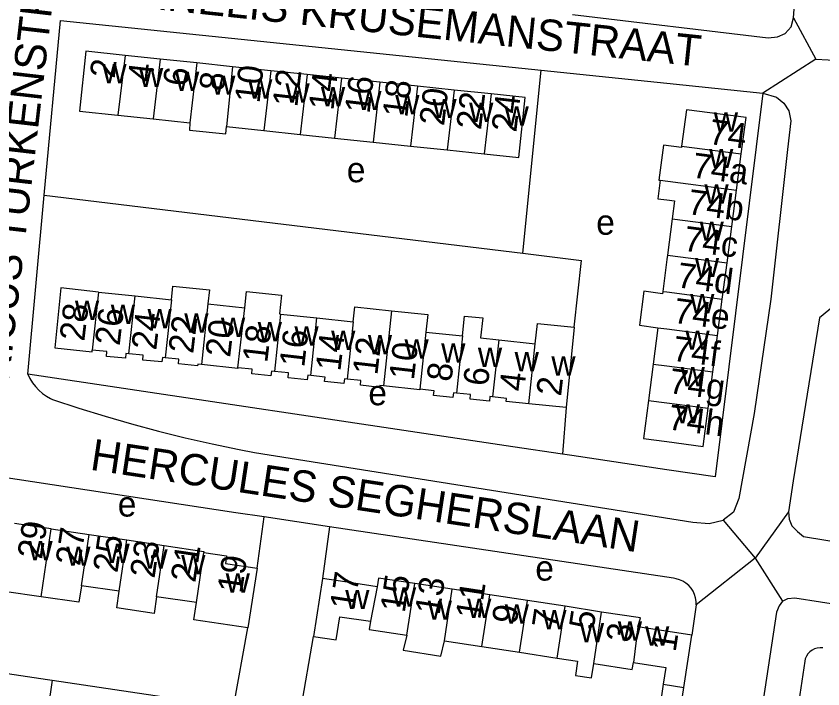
# Model space of a CAD drawing. Extents: x 163012 to 165277, y 382513 to 383987.
# Drawn here: x 163246.1 to 163374.9, y 383224 to 383331.4 of the extents above; entities that cross this region are included whole.
import ezdxf

# ---------------------------------------------------------------- set-up
doc = ezdxf.new("R2010")
doc.units = 0
for name, color, linetype in [('BLT_Basislijn', 7, 'Continuous'), ('BLT_Bebouwing', 7, 'Continuous'), ('BLT_Centroide', 7, 'Continuous'), ('BLT_Huisnummer', 7, 'Continuous'), ('BLT_Huisnummer_ tussenligend', 7, 'Continuous'), ('BLT_Onderverdeling_panden', 7, 'Continuous'), ('BLT_Straatnaam', 7, 'Continuous'), ('BLT_Vlakafsluiter', 7, 'Continuous')]:
    doc.layers.add(name, color=color, linetype=linetype)

msp = doc.modelspace()

# ---------------------------------------------------------------- linework, layer by layer
at = {"layer": 'BLT_Basislijn'}
for p, q in [((163250.62, 383302.77), (163253.2, 383330.67)), ((163253.2, 383330.67), (163329.96, 383322.72)), ((163327.02, 383293.5), (163329.96, 383322.72)), ((163329.96, 383322.72), (163350, 383320.64)), ((163247.99, 383274.21), (163250.62, 383302.77)), ((163250.62, 383302.77), (163327.02, 383293.5)), ((163327.02, 383293.5), (163336.38, 383292.33)), ((163335.19, 383281.7), (163336.38, 383292.33)), ((163379.1, 383287.13), (163374.38, 383283.18)), ((163325.42, 383262.62), (163247.99, 383274.21)), ((163333.94, 383268.86), (163333.34, 383261.44)), ((163333.34, 383261.44), (163325.42, 383262.62)), ((163334.85, 383261.21), (163333.34, 383261.44)), ((163350, 383258.95), (163334.85, 383261.21)), ((163357.71, 383257.79), (163350, 383258.95)), ((163281.2, 383252.08), (163240.34, 383258.32)), ((163285.7, 383251.41), (163281.2, 383252.08)), ((163284.58, 383243.24), (163285.7, 383251.41)), ((163296.15, 383249.84), (163285.7, 383251.41)), ((163296.15, 383249.84), (163295.02, 383241.61)), ((163350, 383241.78), (163296.15, 383249.84)), ((163351.05, 383241.63), (163350, 383241.78)), ((163354.7, 383237.36), (163353.96, 383232.55)), ((163280.84, 383221.02), (163283.14, 383233.7)), ((163291.43, 383219.86), (163293.58, 383232.33)), ((163372.01, 383228.39), (163368.01, 383201.4)), ((163251.88, 383225.34), (163249.99, 383212.44)), ((163251.88, 383225.34), (163280.84, 383221.02))]:
    msp.add_line(p, q, dxfattribs=at)
for points in [[(163370.2, 383331.1), (163375.21, 383397.63), (163379.98, 383443.37), (163379.47, 383447.48), (163378.38, 383448.91), (163376.87, 383450.09), (163374.9, 383450.62)], [(163334.93, 383331.61), (163366.16, 383327.92), (163367.65, 383328.08), (163368.88, 383328.58), (163369.86, 383329.67), (163370.2, 383331.1)], [(163350, 383320.64), (163365.31, 383319.06)], [(163365.31, 383319.06), (163357.71, 383257.79)], [(163365.31, 383319.06), (163367.49, 383318.41), (163368.65, 383317.47), (163369.45, 383316.22), (163369.78, 383314.65), (163369.27, 383310.06), (163366.6, 383286.2), (163363.93, 383267.93), (163361.51, 383254.36), (163360.61, 383252.18), (163358.98, 383250.87)], [(163374.38, 383283.18), (163370.14, 383257.16), (163369.43, 383252.25)], [(163247.99, 383274.21), (163248.33, 383273.51), (163248.73, 383272.84), (163249.2, 383272.22), (163249.74, 383271.65), (163250.33, 383271.14), (163250.96, 383270.69), (163251.64, 383270.3), (163251.93, 383270.17)], [(163251.93, 383270.17), (163256.12, 383268.79), (163260.34, 383267.49), (163264.57, 383266.27), (163268.83, 383265.13), (163273.11, 383264.06), (163277.41, 383263.07), (163281.72, 383262.16), (163284.16, 383261.68)], [(163284.16, 383261.68), (163354.12, 383250.58), (163356.74, 383250.36), (163358.98, 383250.87)], [(163369.43, 383252.25), (163369.53, 383251.03), (163369.96, 383249.99), (163370.84, 383249.08), (163371.8, 383248.31)], [(163371.8, 383248.31), (163405.82, 383242.7), (163463.3, 383234.3)], [(163354.7, 383237.36), (163354.69, 383237.93), (163354.59, 383238.5), (163354.42, 383239.04), (163354.17, 383239.56), (163353.86, 383240.04), (163353.48, 383240.47), (163353.04, 383240.84), (163352.56, 383241.15), (163352.04, 383241.39), (163351.49, 383241.55), (163351.05, 383241.63)], [(163368.47, 383237.95), (163369.3, 383238.38), (163370.44, 383238.51), (163378.6, 383237.22)], [(163368.47, 383237.95), (163367.9, 383237.24), (163367.52, 383236.23), (163353.87, 383146.27)], [(163374.9, 383230.51), (163374.45, 383230.54), (163374, 383230.48), (163373.57, 383230.35), (163373.17, 383230.15), (163372.81, 383229.88), (163372.5, 383229.54), (163372.26, 383229.16), (163372.09, 383228.75), (163372.01, 383228.39)], [(163225.21, 383229.34), (163251.12, 383225.45), (163251.88, 383225.34)]]:
    msp.add_lwpolyline(points, dxfattribs=at)
at = {"layer": 'BLT_Bebouwing'}
for p, q in [((163269.12, 383324.5), (163263.51, 383325.09)), ((163274.99, 383323.88), (163269.12, 383324.5)), ((163280.65, 383323.28), (163274.99, 383323.88)), ((163286.79, 383322.64), (163280.65, 383323.28)), ((163292.59, 383322.02), (163286.79, 383322.64)), ((163298.09, 383321.45), (163292.59, 383322.02)), ((163304.21, 383320.8), (163298.09, 383321.45)), ((163310.2, 383320.17), (163304.21, 383320.8)), ((163316.06, 383319.55), (163310.2, 383320.17)), ((163321.93, 383318.93), (163316.06, 383319.55)), ((163256.27, 383316.19), (163262.39, 383315.54)), ((163262.39, 383315.54), (163268.01, 383314.95)), ((163353.11, 383316.42), (163352.36, 383310.62)), ((163362.63, 383315.18), (163353.11, 383316.42)), ((163268.01, 383314.95), (163273.87, 383314.33)), ((163361.87, 383309.38), (163362.63, 383315.18)), ((163279.72, 383313.72), (163285.67, 383313.09)), ((163285.67, 383313.09), (163291.48, 383312.48)), ((163291.48, 383312.48), (163296.97, 383311.9)), ((163296.97, 383311.9), (163303.1, 383311.25)), ((163303.1, 383311.25), (163309.08, 383310.62)), ((163309.08, 383310.62), (163314.95, 383310.01)), ((163314.95, 383310.01), (163320.82, 383309.39)), ((163361.12, 383303.58), (163361.87, 383309.38)), ((163360.36, 383297.78), (163361.12, 383303.58)), ((163350.85, 383299.02), (163350.09, 383293.22)), ((163359.6, 383291.98), (163360.36, 383297.78)), ((163350, 383292.52), (163349.34, 383287.41)), ((163350.09, 383293.22), (163350, 383292.52)), ((163358.85, 383286.18), (163359.6, 383291.98)), ((163259.29, 383287.31), (163265.11, 383286.69)), ((163265.11, 383286.69), (163270.93, 383286.06)), ((163358.09, 383280.38), (163358.85, 383286.18)), ((163276.74, 383285.44), (163282.66, 383284.8)), ((163288.33, 383283.8), (163294.14, 383283.18)), ((163294.14, 383283.18), (163299.95, 383282.56)), ((163311.53, 383280.92), (163317.36, 383280.3)), ((163335.19, 383281.7), (163333.94, 383268.86)), ((163348.58, 383281.62), (163347.82, 383275.82)), ((163323.16, 383279.67), (163328.99, 383279.05)), ((163357.34, 383274.58), (163358.09, 383280.38)), ((163347.82, 383275.82), (163347.07, 383270.02)), ((163356.58, 383268.77), (163357.34, 383274.58)), ((163355.79, 383262.68), (163356.58, 383268.77)), ((163350, 383263.43), (163355.79, 383262.68)), ((163251.73, 383249.52), (163257.77, 383248.63)), ((163257.77, 383248.63), (163263.79, 383247.74)), ((163263.79, 383247.74), (163269.75, 383246.86)), ((163284.58, 383243.24), (163283.14, 383233.7)), ((163295.02, 383241.61), (163293.58, 383232.33)), ((163315.75, 383239.88), (163309.75, 383240.79)), ((163250.11, 383238.67), (163244.24, 383239.53)), ((163262.57, 383239.54), (163256.54, 383240.43)), ((163321.74, 383238.97), (163315.75, 383239.88)), ((163274.9, 383237.73), (163268.53, 383238.67)), ((163327.74, 383238.06), (163321.74, 383238.97)), ((163333.74, 383237.16), (163327.74, 383238.06)), ((163339.58, 383236.23), (163333.74, 383237.16)), ((163353.96, 383232.55), (163345.37, 383233.85)), ((163314.49, 383231.61), (163320.49, 383230.71)), ((163352.7, 383224.19), (163353.96, 383232.55)), ((163320.49, 383230.71), (163326.49, 383229.8)), ((163326.49, 383229.8), (163332.48, 383228.89)), ((163350.75, 383211.22), (163352.7, 383224.19))]:
    msp.add_line(p, q, dxfattribs=at)
for points in [[(163263.51, 383325.09), (163257.27, 383325.74), (163256.27, 383316.19)], [(163320.82, 383309.39), (163326.37, 383308.8), (163327.38, 383318.36), (163321.93, 383318.93)], [(163273.87, 383314.33), (163273.78, 383313.18), (163279.59, 383312.56), (163279.72, 383313.72)], [(163352.36, 383310.62), (163352.32, 383310.39), (163349.44, 383310.77), (163348.71, 383305.19), (163348.93, 383305.17)], [(163348.93, 383305.17), (163348.54, 383302.18), (163350, 383302.02)], [(163350, 383302.02), (163351.22, 383301.85), (163350.85, 383299.02)], [(163270.93, 383286.06), (163271.17, 383288.27), (163276.98, 383287.65), (163276.74, 383285.44)], [(163259.29, 383287.31), (163253.28, 383287.96), (163252.29, 383278.41), (163258.26, 383277.78), (163258.29, 383278.06)], [(163282.66, 383284.8), (163282.92, 383287.41), (163288.48, 383286.81), (163288.16, 383283.82), (163288.33, 383283.8)], [(163349.34, 383287.41), (163349.28, 383287.05), (163346.33, 383287.44), (163345.62, 383282.01), (163348.58, 383281.62)], [(163299.95, 383282.56), (163300.2, 383284.93), (163306.03, 383284.32)], [(163306.03, 383284.32), (163311.83, 383283.71), (163311.53, 383280.92)], [(163317.36, 383280.3), (163317.7, 383283.48), (163320.6, 383283.17), (163320.26, 383279.99), (163323.16, 383279.67)], [(163328.99, 383279.05), (163329.33, 383282.31), (163335.19, 383281.7)], [(163264.12, 383277.44), (163263.65, 383277.48), (163263.59, 383276.77), (163260.53, 383277.04), (163260.6, 383277.82), (163258.29, 383278.06)], [(163269.94, 383276.83), (163269.47, 383276.88), (163269.39, 383276.15), (163266.33, 383276.45), (163266.4, 383277.23), (163264.12, 383277.44)], [(163275.71, 383275.76), (163275.13, 383275.82), (163275.09, 383275.54), (163272.04, 383275.87), (163272.12, 383276.61), (163269.94, 383276.83)], [(163281.52, 383275.23), (163281.51, 383275.12), (163275.71, 383275.76)], [(163287.36, 383274.62), (163286.87, 383274.67), (163286.8, 383273.94), (163283.74, 383274.24), (163283.82, 383275), (163281.52, 383275.23)], [(163293.16, 383274), (163292.68, 383274.06), (163292.59, 383273.3), (163289.55, 383273.63), (163289.63, 383274.39), (163287.36, 383274.62)], [(163298.99, 383273.41), (163298.52, 383273.46), (163298.43, 383272.7), (163295.37, 383273.04), (163295.44, 383273.75), (163293.16, 383274)], [(163304.75, 383272.32), (163304.19, 383272.39), (163304.16, 383272.09), (163301.08, 383272.43), (163301.16, 383273.17), (163298.99, 383273.41)], [(163310.57, 383271.81), (163310.56, 383271.7), (163304.75, 383272.32)], [(163316.4, 383271.19), (163315.93, 383271.24), (163315.85, 383270.48), (163312.77, 383270.82), (163312.85, 383271.56), (163310.57, 383271.81)], [(163322.15, 383270.59), (163321.76, 383270.64), (163321.67, 383269.87), (163318.59, 383270.23), (163318.67, 383270.94), (163316.4, 383271.19)], [(163327.99, 383269.48), (163324.33, 383269.86), (163324.38, 383270.34), (163322.15, 383270.59)], [(163333.94, 383268.86), (163327.99, 383269.48)], [(163347.07, 383270.02), (163346.27, 383263.92), (163350, 383263.43)], [(163251.73, 383249.52), (163248.36, 383250), (163245.86, 383250.39)], [(163269.75, 383246.86), (163276.11, 383245.92), (163276.08, 383245.74)], [(163276.08, 383245.74), (163279.71, 383245.2), (163279.53, 383243.99), (163284.58, 383243.24)], [(163303.76, 383240.28), (163300.02, 383240.85), (163295.02, 383241.61)], [(163309.75, 383240.79), (163303.97, 383241.66), (163303.76, 383240.28)], [(163256.54, 383240.43), (163256.15, 383237.78), (163250.11, 383238.67)], [(163268.53, 383238.67), (163268.14, 383236.02), (163262.18, 383236.9), (163262.57, 383239.54)], [(163283.14, 383233.7), (163274.49, 383234.97), (163274.9, 383237.73)], [(163293.58, 383232.33), (163297.19, 383231.78), (163297.78, 383235.49), (163302.67, 383234.75)], [(163345.37, 383233.85), (163345.78, 383235.3), (163339.58, 383236.23)], [(163302.67, 383234.75), (163302.5, 383233.43), (163308.5, 383232.52)], [(163308.5, 383232.52), (163307.92, 383230.12), (163313.92, 383229.21), (163314.49, 383231.61)], [(163332.48, 383228.89), (163335.74, 383228.4), (163335.39, 383226.11), (163337.98, 383225.72), (163338.33, 383228)], [(163338.33, 383228), (163344.47, 383227.07), (163344.66, 383228.16)], [(163344.66, 383228.16), (163349.81, 383227.4), (163349.42, 383224.69)], [(163349.42, 383224.69), (163348.28, 383216.92), (163341.9, 383217.89), (163341.09, 383212.77), (163350.75, 383211.22)]]:
    msp.add_lwpolyline(points, dxfattribs=at)
at = {"layer": 'BLT_Onderverdeling_panden'}
for p, q in [((163263.51, 383325.09), (163262.39, 383315.54)), ((163269.12, 383324.5), (163268.01, 383314.95)), ((163274.99, 383323.88), (163273.87, 383314.33)), ((163280.65, 383323.28), (163279.72, 383313.72)), ((163286.79, 383322.64), (163285.67, 383313.09)), ((163292.59, 383322.02), (163291.48, 383312.48)), ((163298.09, 383321.45), (163296.97, 383311.9)), ((163304.21, 383320.8), (163303.1, 383311.25)), ((163310.2, 383320.17), (163309.08, 383310.62)), ((163316.06, 383319.55), (163314.95, 383310.01)), ((163321.93, 383318.93), (163320.82, 383309.39)), ((163352.36, 383310.62), (163361.87, 383309.38)), ((163348.93, 383305.17), (163361.12, 383303.58)), ((163350.85, 383299.02), (163360.36, 383297.78)), ((163350.09, 383293.22), (163359.6, 383291.98)), ((163259.29, 383287.31), (163258.29, 383278.06)), ((163349.34, 383287.41), (163350, 383287.33)), ((163350, 383287.33), (163358.85, 383286.18)), ((163264.12, 383277.44), (163265.11, 383286.69)), ((163270.93, 383286.06), (163269.94, 383276.83)), ((163276.74, 383285.44), (163275.71, 383275.76)), ((163281.52, 383275.23), (163282.66, 383284.8)), ((163288.33, 383283.8), (163287.36, 383274.62)), ((163293.16, 383274), (163294.14, 383283.18)), ((163306.03, 383284.32), (163304.75, 383272.32)), ((163299.95, 383282.56), (163298.99, 383273.41)), ((163311.53, 383280.92), (163310.57, 383271.81)), ((163348.58, 383281.62), (163350, 383281.43)), ((163350, 383281.43), (163358.09, 383280.38)), ((163317.36, 383280.3), (163316.4, 383271.19)), ((163323.16, 383279.67), (163322.15, 383270.59)), ((163327.99, 383269.48), (163328.99, 383279.05)), ((163347.82, 383275.82), (163350, 383275.53)), ((163350, 383275.53), (163357.34, 383274.58)), ((163347.07, 383270.02), (163350, 383269.63)), ((163350, 383269.63), (163356.58, 383268.77)), ((163250.11, 383238.67), (163251.73, 383249.52)), ((163256.54, 383240.43), (163257.77, 383248.63)), ((163262.57, 383239.54), (163263.79, 383247.74)), ((163268.53, 383238.67), (163269.75, 383246.86)), ((163274.9, 383237.73), (163276.08, 383245.74)), ((163308.5, 383232.52), (163309.75, 383240.79)), ((163303.76, 383240.28), (163302.67, 383234.75)), ((163314.49, 383231.61), (163315.75, 383239.88)), ((163320.49, 383230.71), (163321.74, 383238.97)), ((163326.49, 383229.8), (163327.74, 383238.06)), ((163332.48, 383228.89), (163333.74, 383237.16)), ((163338.33, 383228), (163339.58, 383236.23)), ((163345.37, 383233.85), (163344.66, 383228.16)), ((163349.42, 383224.69), (163352.7, 383224.19))]:
    msp.add_line(p, q, dxfattribs=at)
at = {"layer": 'BLT_Vlakafsluiter'}
for p, q in [((163373.78, 383324.5), (163377.71, 383324.28)), ((163369.43, 383252.25), (163364.09, 383244.82)), ((163358.98, 383250.87), (163364.09, 383244.82)), ((163364.09, 383244.82), (163354.7, 383237.36)), ((163364.09, 383244.82), (163368.47, 383237.95))]:
    msp.add_line(p, q, dxfattribs=at)
for points in [[(163370.2, 383331.1), (163373.78, 383324.5)], [(163373.78, 383324.5), (163365.31, 383319.06)]]:
    msp.add_lwpolyline(points, dxfattribs=at)

# ---------------------------------------------------------------- texts
at = {"layer": 'BLT_Centroide'}
for s, p in [('w', (163259.89, 383320.64)), ('w', (163265.75, 383320.02)), ('w', (163271.5, 383319.42)), ('w', (163277.27, 383318.8)), ('w', (163283.16, 383318.19)), ('w', (163289.12, 383317.55)), ('w', (163294.78, 383316.95)), ('w', (163300.59, 383316.36)), ('w', (163306.64, 383315.7)), ('w', (163312.58, 383315.08)), ('w', (163318.44, 383314.47)), ('w', (163324.09, 383313.88)), ('w', (163357.49, 383312.91)), ('w', (163356.74, 383307.09)), ('e', (163298.91, 383304.84)), ('w', (163355.99, 383301.41)), ('e', (163338.72, 383296.46)), ('w', (163355.23, 383295.5)), ('w', (163354.47, 383289.69)), ('w', (163353.71, 383283.91)), ('w', (163255.52, 383282.86)), ('w', (163261.25, 383282.2)), ('w', (163267.11, 383281.52)), ('w', (163272.97, 383280.83)), ('w', (163278.83, 383280.14)), ('w', (163284.69, 383279.45)), ('w', (163290.55, 383278.77)), ('w', (163296.41, 383278.08)), ('w', (163352.96, 383278.09)), ('w', (163302.27, 383277.39)), ('w', (163308.12, 383276.7)), ('w', (163313.98, 383276.03)), ('w', (163319.84, 383275.34)), ('w', (163325.7, 383274.66)), ('w', (163331.56, 383273.97)), ('w', (163352.2, 383272.28)), ('e', (163302.35, 383269.24)), ('w', (163351.43, 383266.34)), ('e', (163262.35, 383251.47)), ('w', (163248.09, 383244.5)), ('w', (163260.39, 383244.05)), ('w', (163254.14, 383243.61)), ('w', (163266.44, 383243.16)), ('w', (163272.48, 383242.27)), ('e', (163329, 383241.25)), ('w', (163279.58, 383239.34)), ('w', (163298.66, 383236.69)), ('w', (163306.12, 383237.11)), ('w', (163311.83, 383235)), ('w', (163318.12, 383235.3)), ('w', (163324.11, 383234.39)), ('w', (163330.11, 383233.48)), ('w', (163336.11, 383231.39)), ('w', (163342.17, 383231.66)), ('w', (163346.52, 383230.88))]:
    msp.add_text(s, height=4, dxfattribs=at).set_placement(p)
at = {"layer": 'BLT_Huisnummer'}
for s, rotation, p in [('2', 83.3315, (163261.85, 383321.33)), ('6', 83.3315, (163273.52, 383320.04)), ('10', 83.3315, (163284.97, 383317.36)), ('14', 83.3315, (163296.77, 383316.21)), ('18', 83.3315, (163308.56, 383315.06)), ('24', 83.3315, (163325.96, 383312.72)), ('74', 352.5735, (163356.56, 383310.97)), ('74b', 352.5735, (163353.18, 383299.78)), ('74d', 352.5713, (163351.46, 383288.09)), ('28', 83.3303, (163257.01, 383279.36)), ('22', 83.3303, (163274.39, 383277.38)), ('18', 83.3303, (163286.21, 383275.93)), ('14', 83.3303, (163297.88, 383274.57)), ('10', 83.3303, (163309.61, 383273.16)), ('74f', 352.5701, (163350.76, 383276.37)), ('6', 83.3303, (163321.43, 383272.18)), ('2', 83.3303, (163333.1, 383270.59)), ('74h', 352.5766, (163350.03, 383265.41)), ('27', 81.589, (163256.33, 383243.5)), ('23', 81.5849, (163268.21, 383241.51)), ('19', 81.6415, (163282.17, 383239.1)), ('17', 81.3862, (163300.11, 383236.42)), ('13', 81.3852, (163313.71, 383235.65)), ('9', 81.3852, (163325.99, 383234.18)), ('5', 81.3841, (163338.29, 383233.29)), ('3', 81.3865, (163344.19, 383231.22)), ('1', 81.3865, (163351.39, 383229.75))]:
    msp.add_text(s, height=4, rotation=rotation, dxfattribs=at).set_placement(p)
at = {"layer": 'BLT_Huisnummer_ tussenligend'}
for s, rotation, p in [('4', 83.3315, (163267.88, 383320.68)), ('8', 83.3315, (163279.29, 383319.28)), ('12', 83.3315, (163291, 383316.74)), ('16', 83.3315, (163302.54, 383315.7)), ('20', 83.3315, (163314.43, 383313.74)), ('22', 83.3315, (163320.33, 383313.11)), ('74a', 352.5735, (163353.89, 383305.62)), ('74c', 352.5777, (163352.53, 383293.92)), ('74e', 352.5713, (163350.93, 383282.42)), ('26', 83.3303, (163262.65, 383278.65)), ('24', 83.3303, (163268.49, 383277.94)), ('20', 83.3303, (163280.28, 383276.79)), ('16', 83.3303, (163292.11, 383275.21)), ('12', 83.3303, (163303.78, 383273.95)), ('8', 83.3303, (163315.6, 383272.89)), ('4', 83.3303, (163327.2, 383271.34)), ('74g', 352.5766, (163350.17, 383271.21)), ('29', 81.589, (163250.25, 383244.55)), ('25', 81.5849, (163262.3, 383242.38)), ('21', 81.6415, (163274.72, 383240.83)), ('15', 81.3852, (163308.15, 383236)), ('11', 81.3852, (163320.2, 383234.92)), ('7', 81.3841, (163332.38, 383233.45))]:
    msp.add_text(s, height=4, rotation=rotation, dxfattribs=at).set_placement(p)
at = {"layer": 'BLT_Straatnaam'}
for s, rotation, p in [('HENRICUS TURKENSTRAAT', 83.382, (163243.28, 383258.59)), ('CORNELIS KRUSEMANSTRAAT', 353.9658, (163255.42, 383333.83)), ('HERCULES SEGHERSLAAN', 351.4162, (163257.8, 383258.97))]:
    msp.add_text(s, height=5, rotation=rotation, dxfattribs=at).set_placement(p)

doc.saveas('drawing.dxf')
